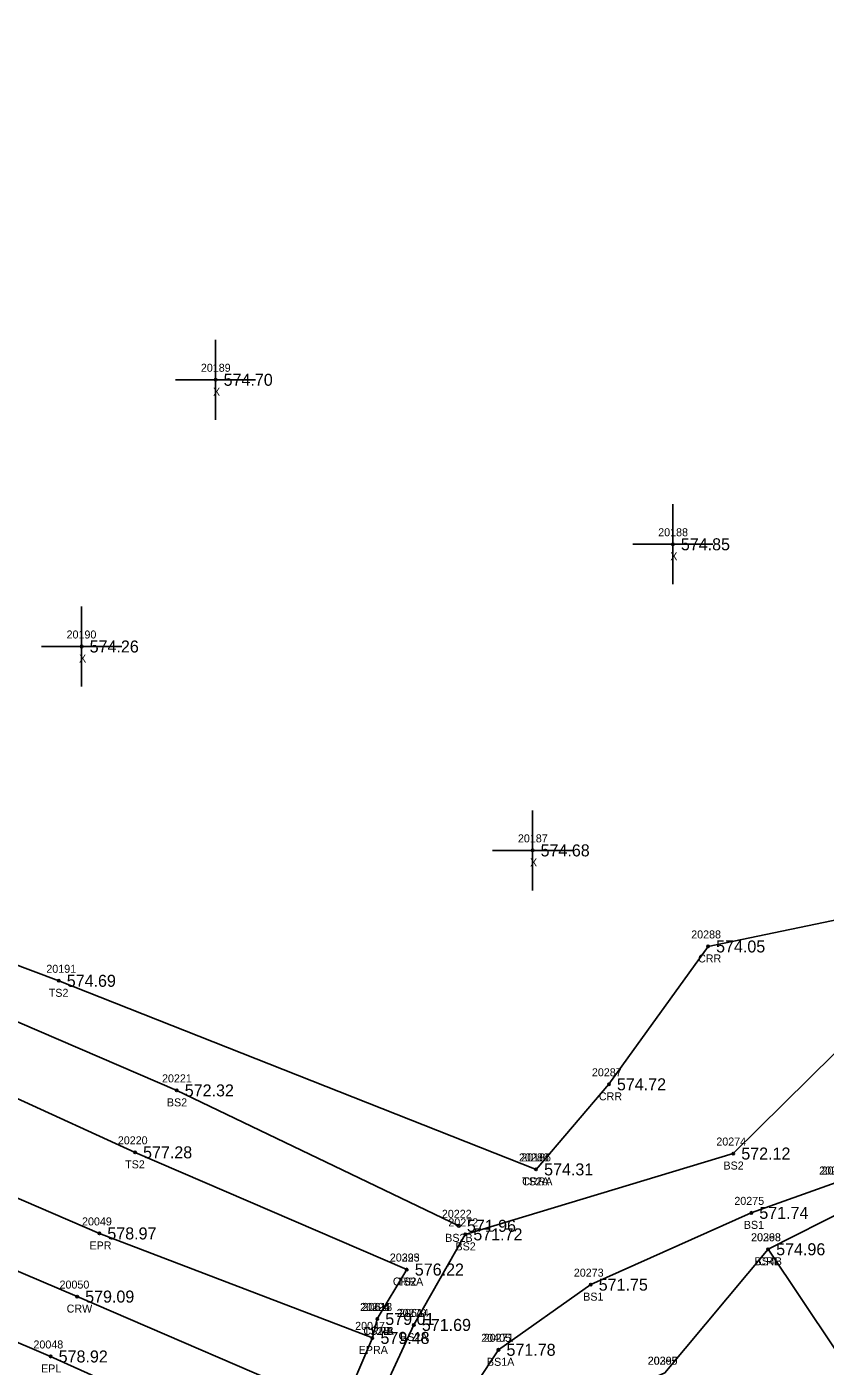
# Model space of a CAD drawing. Extents: x 1664837 to 1666270, y 987403 to 988245.
# Drawn here: x 1665462.9 to 1665562.6, y 987773 to 987940.3 of the extents above; entities that cross this region are included whole.
import ezdxf

# ---------------------------------------------------------------- set-up
doc = ezdxf.new("R2010")
doc.units = 0
for name, color, linetype in [('RD_DTM_BkLn1', 7, 'Continuous'), ('RD_DTM_BkLn2', 7, 'Continuous'), ('RD_DTM_BkLn_txCode', 7, 'Continuous'), ('RD_EX_H2O', 7, 'Continuous'), ('RD_EX_H2O_txCode', 7, 'Continuous'), ('RD_EX_Misc', 7, 'Continuous'), ('RD_EX_Misc_txCode', 7, 'Continuous'), ('RD_EX_Road', 7, 'Continuous'), ('RD_EX_Road_txCode', 7, 'Continuous'), ('RD_EX_TX_H2O_ELEV', 7, 'Continuous'), ('RD_EX_TX_Misc_ELEV', 7, 'Continuous'), ('RD_EX_TX_Road_ELEV', 7, 'Continuous'), ('RD_HC_Survey_ELEV', 7, 'Continuous'), ('RD_HC_Survey_txCode', 7, 'Continuous'), ('RD_SMD_Locator', 7, 'Continuous')]:
    doc.layers.add(name, color=color, linetype=linetype)

msp = doc.modelspace()

# ---------------------------------------------------------------- linework, layer by layer
at = {"layer": 'RD_DTM_BkLn1'}
msp.add_lwpolyline([(1665502.18, 987767.43), (1665469.18, 987781.68), (1665423.29, 987801.23), (1665377.17, 987820.37), (1665331.28, 987839.54), (1665285.44, 987859.03), (1665239.3, 987878.58), (1665193.14, 987897.86), (1665147.41, 987917.57), (1665101.07, 987936.7), (1665055.19, 987956.08), (1665009.23, 987975.83), (1664963.42, 987995.66), (1664917.15, 988015.07), (1664871.41, 988034.69)], dxfattribs=at)
at = {"layer": 'RD_DTM_BkLn2'}
for points in [[(1665511.23, 987778.14), (1665517.66, 987789.45), (1665551.13, 987799.55), (1665566.94, 987815.17), (1665584.37, 987828.05), (1665587.06, 987846.74), (1665590.03, 987866.53), (1665606.32, 987897.21), (1665626.52, 987926.63), (1665648.51, 987960.46), (1665641.85, 987993.37), (1665649.56, 988007.84), (1665641.39, 988045.42), (1665662.4, 988073.33), (1665687.13, 988124.22), (1665718.46, 988169.29), (1665714.8, 988227.5)], [(1665526.5, 987797.57), (1665466.88, 987821.13), (1665430.93, 987834.67), (1665385.41, 987852.45), (1665344.34, 987868.11), (1665298.9, 987885.03), (1665253.91, 987902.76), (1665220.99, 987915.86), (1665188.5, 987922.98), (1665151.7, 987937.17), (1665150.15, 987932.64), (1665154.49, 987927.34), (1665198.68, 987910.11), (1665245.58, 987892.26), (1665291.48, 987872.02), (1665339.41, 987857.06), (1665385.96, 987838.24), (1665430.55, 987820.66), (1665476.41, 987799.7), (1665510.35, 987785.06), (1665506.66, 987778.89)], [(1665151.94, 987933.71), (1665201.46, 987914.66), (1665247.51, 987895.52), (1665294.62, 987876.98), (1665342.05, 987862.7), (1665388.78, 987843.93), (1665435.12, 987827.47), (1665481.62, 987807.44), (1665516.85, 987790.52)], [(1665521.8, 987775.03), (1665533.32, 987783.17), (1665553.38, 987792.14), (1665563.99, 987795.93)], [(1665937.25, 987616.34), (1665889.99, 987630.17), (1665844.42, 987647.08), (1665801.11, 987667.84), (1665753.91, 987686.95), (1665707.93, 987709.21), (1665661.99, 987726.38), (1665615.37, 987748.93), (1665567.93, 987769.01), (1665555.48, 987787.59)], [(1665511.23, 987778.14), (1665500.12, 987754.08), (1665496.26, 987735.63), (1665475.45, 987718.43), (1665445.39, 987709.52), (1665428.04, 987704.31), (1665389.45, 987688.17), (1665361.39, 987673.13), (1665330.12, 987656.7), (1665283.57, 987647.17), (1665235.53, 987667.53), (1665208.93, 987663.65), (1665168.4, 987630.38), (1665122.54, 987622.98), (1665093.74, 987624.1), (1665049.09, 987603.27)], [(1665521.8, 987775.03), (1665513.35, 987762.3), (1665512.93, 987744.69), (1665504.21, 987730.32), (1665472.11, 987703.59), (1665484.52, 987698.45), (1665513.21, 987703.54), (1665525.98, 987684.44), (1665562.43, 987664.02), (1665594.02, 987677.42), (1665619.36, 987684.18), (1665641.6, 987678.85), (1665662.25, 987650.14), (1665684.59, 987631.79), (1665704.75, 987626.25), (1665722.78, 987589.94)]]:
    msp.add_lwpolyline(points, dxfattribs=at)
at = {"layer": 'RD_EX_H2O'}
for p, q in [((1665510.35, 987785.06), (1665506.66, 987778.89)), ((1665506.66, 987778.89), (1665506.06, 987776.52))]:
    msp.add_line(p, q, dxfattribs=at)
for points in [[(1665526.5, 987797.57), (1665535.59, 987808.2), (1665547.98, 987825.42), (1665568.59, 987829.69), (1665585.83, 987856.79), (1665584.87, 987866.91), (1665603.81, 987898.8), (1665618.99, 987930.85), (1665645.33, 987961.5), (1665639.67, 987994.37), (1665644.94, 988008.07), (1665639.5, 988048.94), (1665653.76, 988079.25), (1665684.31, 988124.82), (1665706.22, 988174.88), (1665711.8, 988227.54)], [(1665565.69, 987792.78), (1665555.48, 987787.59), (1665542.58, 987772.17), (1665532.86, 987767.81), (1665532.86, 987767.81), (1665531.47, 987764.82)]]:
    msp.add_lwpolyline(points, dxfattribs=at)
at = {"layer": 'RD_EX_Misc'}
for p, q in [((1665486.47, 987891.21), (1665486.47, 987901.21)), ((1665481.47, 987896.21), (1665491.47, 987896.21)), ((1665543.58, 987870.66), (1665543.58, 987880.66)), ((1665538.58, 987875.66), (1665548.58, 987875.66)), ((1665469.74, 987857.89), (1665469.74, 987867.89)), ((1665464.74, 987862.89), (1665474.74, 987862.89)), ((1665526.06, 987832.42), (1665526.06, 987842.42)), ((1665521.06, 987837.42), (1665531.06, 987837.42))]:
    msp.add_line(p, q, dxfattribs=at)
at = {"layer": 'RD_EX_Road'}
for points in [[(1665506.06, 987776.52), (1665471.95, 987789.57), (1665426.52, 987809.19), (1665380.33, 987828.78), (1665335.61, 987847.53), (1665288.25, 987866.82), (1665242.34, 987886.56), (1665197.07, 987906.16), (1665152.2, 987925.43), (1665127.55, 987936.7), (1665104.5, 987945.2), (1665059.19, 987965.3), (1665013.63, 987984.66), (1664966.38, 988005.06), (1664921.66, 988023.83), (1664875.55, 988043.8)], [(1665498.75, 987759.37), (1665465.87, 987774.2), (1665419.78, 987793.88), (1665373.62, 987813.14), (1665327.95, 987832.31), (1665281.42, 987852.3), (1665236.13, 987871.34), (1665189.6, 987890.71), (1665143.92, 987909.97), (1665117.43, 987920.99), (1665086.22, 987934.27), (1665051.62, 987948.55), (1665005.38, 987968.44), (1664960.17, 987987.67), (1664913.53, 988007.62), (1664868.21, 988026.81)], [(1665506.06, 987776.52), (1665502.18, 987767.43), (1665498.75, 987759.37)]]:
    msp.add_lwpolyline(points, dxfattribs=at)
at = {"layer": 'RD_SMD_Locator'}
for centre in [(1665486.47, 987896.21), (1665543.58, 987875.66), (1665469.74, 987862.89), (1665526.06, 987837.42), (1665547.98, 987825.42), (1665466.88, 987821.13), (1665535.59, 987808.2), (1665481.62, 987807.44), (1665476.41, 987799.7), (1665551.13, 987799.55), (1665526.5, 987797.57), (1665526.5, 987797.57), (1665553.38, 987792.14), (1665516.85, 987790.52), (1665471.95, 987789.57), (1665517.66, 987789.45), (1665555.48, 987787.59), (1665555.48, 987787.59), (1665510.35, 987785.06), (1665510.35, 987785.06), (1665533.32, 987783.17), (1665469.18, 987781.68), (1665506.66, 987778.89), (1665506.66, 987778.89), (1665506.66, 987778.89), (1665511.23, 987778.14), (1665511.23, 987778.14), (1665506.06, 987776.52), (1665521.8, 987775.03), (1665521.8, 987775.03), (1665465.87, 987774.2)]:
    msp.add_circle(centre, 0.15, dxfattribs=at)

# ---------------------------------------------------------------- texts
at = {"layer": 'RD_DTM_BkLn_txCode'}
for s, p in [('20191', (1665465.33, 987822.13)), ('TS2', (1665465.63, 987819.13)), ('20221', (1665479.78, 987808.44)), ('BS2', (1665480.39, 987805.44)), ('20220', (1665474.26, 987800.7)), ('20274', (1665549.01, 987800.55)), ('TS2', (1665475.17, 987797.7)), ('20186', (1665524.64, 987798.57)), ('BS2', (1665549.9, 987797.55)), ('TS2A', (1665524.77, 987795.57)), ('20276', (1665561.85, 987796.93)), ('20185', (1665562.16, 987796.93)), ('20275', (1665551.26, 987793.14)), ('20222', (1665514.73, 987791.52)), ('20272', (1665515.54, 987790.45)), ('BS1', (1665552.44, 987790.14)), ('BS2B', (1665515.15, 987788.52)), ('BS2', (1665516.43, 987787.45)), ('20263', (1665553.34, 987788.59)), ('20223', (1665508.23, 987786.06)), ('BS4B', (1665553.78, 987785.59)), ('20273', (1665531.21, 987784.17)), ('TS2', (1665509.11, 987783.06)), ('BS1', (1665532.38, 987781.17)), ('20224', (1665504.54, 987779.89)), ('20270', (1665509.08, 987779.14)), ('20614', (1665509.38, 987779.14)), ('TS2B', (1665504.94, 987776.89)), ('BS2A', (1665509.52, 987776.14)), ('BS2A', (1665509.52, 987776.14)), ('20405', (1665519.64, 987776.03)), ('20271', (1665519.96, 987776.03)), ('BS1A', (1665520.36, 987773.03)), ('BS1A', (1665520.36, 987773.03)), ('20265', (1665540.43, 987773.17))]:
    msp.add_text(s, height=1, dxfattribs=at).set_placement(p)
at = {"layer": 'RD_EX_H2O_txCode'}
for s, p in [('20288', (1665545.87, 987826.42)), ('CRR', (1665546.73, 987823.42)), ('20287', (1665533.47, 987809.2)), ('CRR', (1665534.34, 987806.2)), ('20286', (1665524.36, 987798.57)), ('CRRA', (1665524.76, 987795.57)), ('20398', (1665553.36, 987788.59)), ('20395', (1665508.23, 987786.06)), ('CRL', (1665554.25, 987785.59)), ('CRRA', (1665508.61, 987783.06)), ('20396', (1665504.52, 987779.89)), ('20618', (1665504.8, 987779.89)), ('CRRA', (1665504.92, 987776.89)), ('CRRB', (1665504.93, 987776.89)), ('20399', (1665540.46, 987773.17))]:
    msp.add_text(s, height=1, dxfattribs=at).set_placement(p)
at = {"layer": 'RD_EX_Misc_txCode'}
for s, p in [('20189', (1665484.63, 987897.21)), ('X', (1665486.15, 987894.21)), ('20188', (1665541.75, 987876.66)), ('X', (1665543.26, 987873.66)), ('20190', (1665467.86, 987863.89)), ('X', (1665469.42, 987860.89)), ('20187', (1665524.23, 987838.42)), ('X', (1665525.74, 987835.42))]:
    msp.add_text(s, height=1, dxfattribs=at).set_placement(p)
at = {"layer": 'RD_EX_Road_txCode'}
for s, p in [('20049', (1665469.79, 987790.57)), ('EPR', (1665470.72, 987787.57)), ('20047', (1665503.9, 987777.52)), ('20048', (1665463.72, 987775.2)), ('EPRA', (1665504.34, 987774.52)), ('EPL', (1665464.67, 987772.2))]:
    msp.add_text(s, height=1, dxfattribs=at).set_placement(p)
at = {"layer": 'RD_EX_TX_H2O_ELEV'}
for s, p in [('574.05', (1665548.98, 987824.67)), ('574.72', (1665536.59, 987807.45)), ('574.31', (1665527.5, 987796.82)), ('574.96', (1665556.48, 987786.84)), ('576.22', (1665511.35, 987784.31)), ('579.01', (1665507.66, 987778.14)), ('579.01', (1665507.66, 987778.14))]:
    msp.add_text(s, height=1.5, dxfattribs=at).set_placement(p)
at = {"layer": 'RD_EX_TX_Misc_ELEV'}
for s, p in [('574.70', (1665487.47, 987895.46)), ('574.85', (1665544.58, 987874.91)), ('574.26', (1665470.74, 987862.14)), ('574.68', (1665527.06, 987836.67)), ('574.69', (1665467.88, 987820.38)), ('572.32', (1665482.62, 987806.69)), ('577.28', (1665477.41, 987798.95)), ('572.12', (1665552.13, 987798.8)), ('574.31', (1665527.5, 987796.82)), ('571.74', (1665554.38, 987791.39)), ('571.96', (1665517.85, 987789.77)), ('571.72', (1665518.66, 987788.7)), ('574.96', (1665556.48, 987786.84)), ('576.22', (1665511.35, 987784.31)), ('571.75', (1665534.32, 987782.42)), ('579.01', (1665507.66, 987778.14)), ('571.69', (1665512.23, 987777.39)), ('571.69', (1665512.23, 987777.39)), ('571.78', (1665522.8, 987774.28)), ('571.78', (1665522.8, 987774.28))]:
    msp.add_text(s, height=1.5, dxfattribs=at).set_placement(p)
at = {"layer": 'RD_EX_TX_Road_ELEV'}
for s, p in [('578.97', (1665472.95, 987788.82)), ('579.48', (1665507.06, 987775.77)), ('578.92', (1665466.87, 987773.45))]:
    msp.add_text(s, height=1.5, dxfattribs=at).set_placement(p)
at = {"layer": 'RD_HC_Survey_ELEV'}
msp.add_text('579.09', height=1.5, dxfattribs=at).set_placement((1665470.18, 987780.93))
at = {"layer": 'RD_HC_Survey_txCode'}
for s, p in [('20050', (1665466.98, 987782.68)), ('CRW', (1665467.87, 987779.68))]:
    msp.add_text(s, height=1, dxfattribs=at).set_placement(p)

doc.saveas('drawing.dxf')
